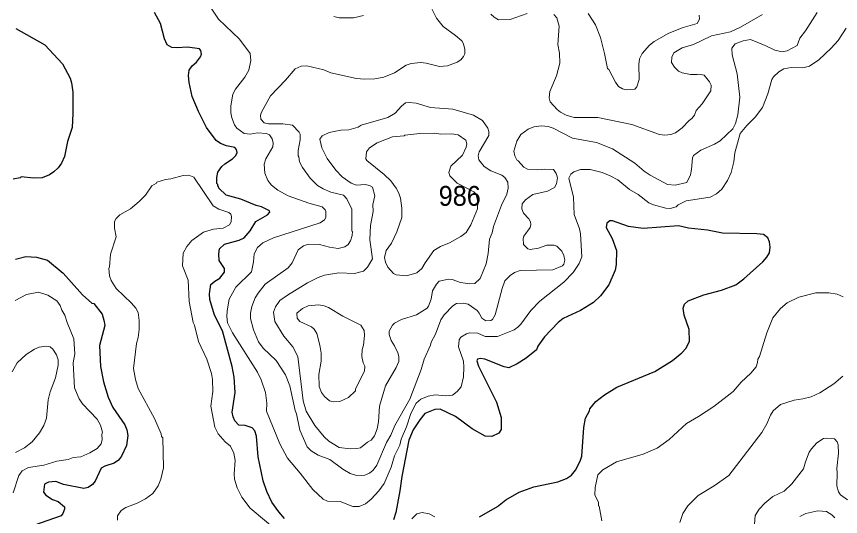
# Model space of a CAD drawing. Extents: x 447.8 to 473.9, y 7733.1 to 7760.8.
# Drawn here: x 456.578 to 459.898, y 7741.122 to 7743.138 of the extents above; entities that cross this region are included whole.
import ezdxf

# ---------------------------------------------------------------- set-up
doc = ezdxf.new("R2010")
doc.units = 0
doc.header["$LTSCALE"] = 0.032
doc.layers.add('1', color=7, linetype='Continuous', lineweight=25)
doc.layers.add('2', color=7, linetype='Continuous', lineweight=13)
doc.layers.add('21', color=7, linetype='Continuous')

msp = doc.modelspace()

# ---------------------------------------------------------------- linework, layer by layer
at = {"layer": '1'}
for points in [[(457.271, 7742.9008), (457.2733, 7742.9223), (457.2854, 7742.9399), (457.3039, 7742.9547), (457.319, 7742.9752), (457.3237, 7742.9862), (457.3213, 7743.0016), (457.3152, 7743.0082), (457.2669, 7743.0153), (457.2261, 7743.0114), (457.2045, 7743.013), (457.1858, 7743.0245), (457.1745, 7743.0482), (457.1587, 7743.1099), (457.1342, 7743.1542)], [(456.5753, 7743.0905), (456.6929, 7743.024), (456.7637, 7742.9477), (456.7947, 7742.8902), (456.8005, 7742.8707), (456.8052, 7742.8333), (456.8051, 7742.7468), (456.802, 7742.6914), (456.7844, 7742.6341), (456.7723, 7742.5744), (456.7597, 7742.5476), (456.7456, 7742.5277), (456.7287, 7742.5117), (456.7113, 7742.5004), (456.6822, 7742.4879), (456.6473, 7742.4871), (456.5969, 7742.4917), (456.5925, 7742.4879), (456.5648, 7742.4822)], [(457.3824, 7742.638), (457.3439, 7742.6914), (457.3114, 7742.7548), (457.2855, 7742.8162), (457.2732, 7742.8725), (457.271, 7742.9008)], [(457.6583, 7741.1137), (457.6354, 7741.1407), (457.6072, 7741.1806), (457.5861, 7741.2226), (457.572, 7741.2661), (457.5514, 7741.3624), (457.545, 7741.4458), (457.5378, 7741.4674), (457.5275, 7741.48), (457.4993, 7741.4891), (457.4736, 7741.491), (457.4582, 7741.5077), (457.4513, 7741.5239), (457.4474, 7741.5429), (457.4592, 7741.623), (457.4545, 7741.6844), (457.4472, 7741.7267), (457.4083, 7741.8714), (457.3761, 7741.9345), (457.3575, 7741.9977), (457.3561, 7742.0208), (457.3615, 7742.0578), (457.3773, 7742.0716), (457.3975, 7742.0831), (457.416, 7742.1075), (457.4158, 7742.1226), (457.395, 7742.1546), (457.3928, 7742.182), (457.3964, 7742.2022), (457.4168, 7742.2204), (457.4759, 7742.2361), (457.4961, 7742.2459), (457.5199, 7742.2738), (457.5419, 7742.3123), (457.59, 7742.3383), (457.5986, 7742.349), (457.5973, 7742.3552), (457.5655, 7742.3707), (457.5439, 7742.3758), (457.4821, 7742.402), (457.4233, 7742.4182), (457.393, 7742.4468), (457.3925, 7742.4525), (457.3888, 7742.4546), (457.3887, 7742.4611), (457.3856, 7742.465), (457.3855, 7742.4887), (457.3892, 7742.5112), (457.4059, 7742.5337), (457.4176, 7742.5447), (457.448, 7742.5649), (457.4615, 7742.5778), (457.4666, 7742.5897), (457.4649, 7742.6015), (457.4573, 7742.6105), (457.4237, 7742.6163), (457.3997, 7742.6259), (457.3824, 7742.638)], [(458.4434, 7741.1209), (458.5159, 7741.1624), (458.5497, 7741.1895), (458.6036, 7741.2204), (458.662, 7741.2415), (458.7586, 7741.2617), (458.7934, 7741.276), (458.8143, 7741.2893), (458.83, 7741.3093), (458.8491, 7741.3461), (458.8556, 7741.3657), (458.8636, 7741.4808), (458.8708, 7741.5192), (458.8867, 7741.549), (458.8873, 7741.5567), (458.9123, 7741.5867), (458.9474, 7741.6134), (458.9964, 7741.6445), (459.1504, 7741.7071), (459.2204, 7741.7516), (459.2582, 7741.782), (459.2743, 7741.7994), (459.2901, 7741.8285), (459.2878, 7741.8767), (459.2686, 7741.9345), (459.2645, 7741.9629), (459.2698, 7741.9786), (459.2841, 7741.9925), (459.3474, 7742.0159), (459.418, 7742.0348), (459.4759, 7742.0571), (459.5079, 7742.0804), (459.5843, 7742.1495), (459.6006, 7742.1686), (459.6117, 7742.1852), (459.6151, 7742.2087), (459.6116, 7742.2296), (459.6045, 7742.2462), (459.5882, 7742.2587), (459.5603, 7742.2624), (459.4223, 7742.265), (459.3622, 7742.277), (459.2861, 7742.2849), (459.2456, 7742.2946), (459.1033, 7742.2835), (459.0432, 7742.2919), (458.9791, 7742.3147), (458.9681, 7742.3146), (458.9567, 7742.3046), (458.9536, 7742.2878), (458.9773, 7742.2429), (458.9951, 7742.1942), (458.9936, 7742.1388), (458.9898, 7742.116), (458.965, 7742.0558), (458.9315, 7742.0122), (458.9024, 7741.9855), (458.8505, 7741.9523), (458.7808, 7741.9201), (458.7601, 7741.9039), (458.7055, 7741.8473)], [(456.574, 7742.1599), (456.616, 7742.1704), (456.6593, 7742.1677), (456.7037, 7742.1558), (456.7665, 7742.1034), (456.8447, 7742.0163), (456.8819, 7741.9831), (456.8901, 7741.9811), (456.9237, 7741.9376), (456.9319, 7741.9088), (456.9335, 7741.8925), (456.9127, 7741.8113), (456.9167, 7741.7276), (456.9286, 7741.6658), (456.9478, 7741.6029), (456.9667, 7741.562), (457.0152, 7741.4923), (457.0231, 7741.4718), (457.0264, 7741.4491), (457.0215, 7741.4086), (457.0018, 7741.366), (456.9889, 7741.3491), (456.9719, 7741.3377), (456.9347, 7741.3254), (456.9194, 7741.3168), (456.8953, 7741.2646), (456.8845, 7741.2518), (456.8672, 7741.2388), (456.8498, 7741.2359), (456.7671, 7741.2517), (456.7362, 7741.263), (456.7067, 7741.2614), (456.6909, 7741.2527), (456.6874, 7741.2207), (456.6969, 7741.2081), (456.7232, 7741.1907), (456.7464, 7741.1824), (456.7711, 7741.1608), (456.7715, 7741.1524), (456.7654, 7741.1346), (456.7579, 7741.1253), (456.6241, 7741.0786)], [(458.7055, 7741.8473), (458.6782, 7741.8088), (458.6725, 7741.7949), (458.6321, 7741.7611), (458.5946, 7741.7377), (458.5614, 7741.7217)], [(458.5614, 7741.7217), (458.5427, 7741.7257), (458.4656, 7741.757), (458.4472, 7741.76), (458.4348, 7741.7573), (458.4326, 7741.7501), (458.4392, 7741.7287), (458.5125, 7741.5837), (458.5302, 7741.5211), (458.5302, 7741.4733), (458.5211, 7741.4585), (458.4925, 7741.4443), (458.4661, 7741.4467), (458.4136, 7741.4765), (458.3471, 7741.5261), (458.2846, 7741.5548), (458.2642, 7741.554), (458.2239, 7741.5377), (458.2026, 7741.5124), (458.1761, 7741.4717), (458.1584, 7741.4302), (458.131, 7741.2839), (458.1231, 7741.2256), (458.1062, 7741.1384), (458.0975, 7741.109)]]:
    msp.add_lwpolyline(points, dxfattribs=at)
at = {"layer": '2'}
for points in [[(457.5203, 7741.9419), (457.5258, 7741.9686), (457.5401, 7742.0034), (457.5518, 7742.0224), (457.5806, 7742.0586), (457.673, 7742.1252), (457.6888, 7742.1454), (457.7131, 7742.1981), (457.7348, 7742.2132), (457.7542, 7742.2201), (457.7988, 7742.2186), (457.8387, 7742.2079), (457.8737, 7742.2026), (457.9011, 7742.2103), (457.914, 7742.2188), (457.9234, 7742.2345), (457.9308, 7742.2555), (457.9314, 7742.2711), (457.9291, 7742.2734), (457.929, 7742.3609), (457.9095, 7742.4032), (457.8955, 7742.4182), (457.8447, 7742.4302), (457.8131, 7742.444), (457.7914, 7742.4575), (457.7611, 7742.486), (457.7301, 7742.5298), (457.7188, 7742.5527), (457.7158, 7742.5724), (457.7127, 7742.5772), (457.7127, 7742.5976), (457.7206, 7742.6414), (457.7206, 7742.6639), (457.7172, 7742.6724), (457.6898, 7742.7002), (457.6507, 7742.7051), (457.5933, 7742.7061), (457.5763, 7742.7102), (457.5623, 7742.7247), (457.5615, 7742.74), (457.5648, 7742.7532), (457.6019, 7742.819), (457.6626, 7742.8819), (457.7003, 7742.9277), (457.7253, 7742.9383), (457.7475, 7742.9392), (457.8159, 7742.9237), (457.8443, 7742.9111), (457.9479, 7742.8879), (457.9808, 7742.8855), (458.0218, 7742.8866), (458.0579, 7742.8942), (458.1015, 7742.9109), (458.148, 7742.942), (458.1676, 7742.9487), (458.2066, 7742.9528), (458.2284, 7742.9501), (458.283, 7742.9368), (458.3151, 7742.9391), (458.3535, 7742.9543), (458.3681, 7742.9639), (458.3793, 7742.9768), (458.3843, 7742.9884), (458.3843, 7743.0057), (458.3795, 7743.0279), (458.3727, 7743.0397), (458.3472, 7743.062), (458.2975, 7743.0981), (458.2699, 7743.132), (458.2362, 7743.1994)], [(457.36, 7743.1761), (457.3917, 7743.1276), (457.4761, 7743.0472), (457.5198, 7742.9888), (457.5217, 7742.9607), (457.5136, 7742.9223), (457.4981, 7742.894), (457.4602, 7742.8458), (457.4497, 7742.8249), (457.4422, 7742.7781), (457.4417, 7742.7493), (457.4453, 7742.7298), (457.4566, 7742.7017), (457.4653, 7742.688), (457.4959, 7742.6664), (457.5196, 7742.6643), (457.5498, 7742.669), (457.5848, 7742.6667), (457.5972, 7742.6606), (457.6088, 7742.645), (457.6122, 7742.6279), (457.6114, 7742.6132), (457.5831, 7742.5645), (457.5763, 7742.5423), (457.5786, 7742.5068), (457.5912, 7742.4772), (457.6053, 7742.4588), (457.631, 7742.4385), (457.6732, 7742.4146), (457.7559, 7742.3861), (457.81, 7742.371), (457.8215, 7742.3591), (457.8246, 7742.3521), (457.8245, 7742.3275), (457.8186, 7742.319), (457.8019, 7742.3058), (457.6133, 7742.2458), (457.5711, 7742.2256), (457.549, 7742.2065)], [(458.4895, 7743.1481), (458.502, 7743.1359), (458.5202, 7743.1251), (458.5664, 7743.1258), (458.6355, 7743.1503)], [(459.8038, 7743.1543), (459.7573, 7743.0804), (459.7334, 7743.0506), (459.7228, 7743.0211), (459.6823, 7742.9998), (459.6633, 7742.9961), (459.6338, 7743.002), (459.5949, 7743.022), (459.5357, 7743.0456), (459.5059, 7743.0407), (459.4741, 7743.0283), (459.4601, 7743.0105), (459.4615, 7742.9843), (459.4815, 7742.907), (459.4922, 7742.8132), (459.4842, 7742.7415), (459.4743, 7742.7072), (459.4639, 7742.6857), (459.413, 7742.6372), (459.3905, 7742.623), (459.3353, 7742.5995), (459.3052, 7742.5774), (459.3014, 7742.568), (459.2981, 7742.5215), (459.2939, 7742.5001)], [(457.9762, 7743.1427), (457.9358, 7743.133), (457.878, 7743.1335), (457.8567, 7743.1389)], [(458.7434, 7743.1458), (458.7544, 7743.1324), (458.7647, 7743.0998), (458.7595, 7743.0254), (458.7658, 7742.99), (458.7666, 7742.9505), (458.7542, 7742.8987), (458.7274, 7742.8354), (458.7243, 7742.8098), (458.7288, 7742.7944), (458.7565, 7742.7628), (458.7696, 7742.7521), (458.7922, 7742.7402), (458.8252, 7742.7316), (458.9204, 7742.7307), (459.0567, 7742.7033), (459.1685, 7742.6627)], [(458.881, 7743.15), (458.9105, 7743.1042), (458.9307, 7743.0534), (458.9477, 7742.9887), (458.9592, 7742.928), (458.9648, 7742.9242), (458.9918, 7742.8729), (459.0036, 7742.8563), (459.0196, 7742.8465), (459.0348, 7742.842), (459.0688, 7742.8447), (459.0777, 7742.8551), (459.0867, 7742.884), (459.085, 7742.9451), (459.0876, 7742.9679), (459.0987, 7742.9898), (459.1282, 7743.0233), (459.1469, 7743.038), (459.2056, 7743.0713), (459.2644, 7743.0938), (459.3202, 7743.1106), (459.3292, 7743.1278), (459.3283, 7743.1436)], [(459.1685, 7742.6627), (459.19, 7742.6595), (459.2142, 7742.6622), (459.2324, 7742.6691), (459.2603, 7742.6898), (459.2875, 7742.7184), (459.2991, 7742.727), (459.3092, 7742.7405), (459.3167, 7742.759), (459.34, 7742.7863), (459.3759, 7742.8381), (459.3766, 7742.8612), (459.3705, 7742.8752), (459.348, 7742.9012), (459.327, 7742.9063), (459.3202, 7742.904), (459.2933, 7742.9047), (459.2603, 7742.9118), (459.2453, 7742.9185), (459.2287, 7742.9339), (459.2164, 7742.9526), (459.2178, 7742.9746), (459.2262, 7742.9914), (459.2602, 7743.012), (459.3052, 7743.0252), (459.3784, 7743.061), (459.4543, 7743.0765), (459.4947, 7743.0951), (459.584, 7743.1464)], [(459.8883, 7743.042), (459.9202, 7743.0908)], [(459.6997, 7742.9326), (459.7457, 7742.9312), (459.7731, 7742.9384), (459.8104, 7742.964), (459.8608, 7743.0113), (459.8883, 7743.042)], [(457.4353, 7741.9985), (457.4264, 7741.9515), (457.4257, 7741.9294), (457.4289, 7741.9027), (457.4486, 7741.8629), (457.5487, 7741.7046), (457.5645, 7741.6735), (457.5819, 7741.6217), (457.5866, 7741.5797), (457.586, 7741.5471), (457.6392, 7741.416), (457.6697, 7741.3571), (457.7217, 7741.2973), (457.7725, 7741.2312), (457.8142, 7741.1916), (457.8318, 7741.1837), (457.8827, 7741.1828), (457.9329, 7741.1628), (457.9581, 7741.1622), (457.9844, 7741.1737), (458.0074, 7741.1916), (458.0384, 7741.2264), (458.0589, 7741.256), (458.0871, 7741.3213), (458.1007, 7741.3675), (458.1219, 7741.4099), (458.1285, 7741.4343), (458.1496, 7741.4841), (458.1664, 7741.5373), (458.189, 7741.58), (458.2074, 7741.5954), (458.2372, 7741.6077), (458.2651, 7741.6124), (458.3083, 7741.6086), (458.3351, 7741.6118), (458.3539, 7741.6263), (458.369, 7741.645), (458.3787, 7741.6849), (458.381, 7741.7241), (458.3786, 7741.7488), (458.3595, 7741.8068), (458.3619, 7741.8342), (458.3678, 7741.8452), (458.3908, 7741.8586), (458.403, 7741.8626), (458.4367, 7741.8609), (458.4662, 7741.8484), (458.5166, 7741.8483), (458.5829, 7741.8751), (458.5983, 7741.8851), (458.6106, 7741.8982), (458.6499, 7741.9526), (458.6859, 7741.9903), (458.7836, 7742.0671), (458.8212, 7742.1062), (458.8445, 7742.1418), (458.8562, 7742.1689), (458.8509, 7742.2626), (458.8466, 7742.2828), (458.8244, 7742.3398), (458.8218, 7742.4095), (458.803, 7742.4865), (458.8117, 7742.5031), (458.8238, 7742.5123), (458.8504, 7742.5214), (458.8895, 7742.5214), (458.9383, 7742.5091), (458.97, 7742.4964), (459.0008, 7742.4793), (459.0471, 7742.4411), (459.0833, 7742.4204), (459.1259, 7742.3873), (459.1443, 7742.3788), (459.1941, 7742.365), (459.2121, 7742.3645), (459.2353, 7742.3711), (459.244, 7742.3789), (459.2766, 7742.3948), (459.3723, 7742.4096), (459.3983, 7742.4238), (459.4196, 7742.4428), (459.4428, 7742.4775), (459.457, 7742.5094), (459.4686, 7742.5528), (459.4716, 7742.589), (459.4941, 7742.6664), (459.5206, 7742.6984), (459.5541, 7742.732), (459.5832, 7742.7713), (459.605, 7742.8265), (459.6212, 7742.8849), (459.6281, 7742.8952), (459.65, 7742.9158), (459.6696, 7742.9271), (459.6997, 7742.9326)], [(458.0736, 7742.7309), (458.1034, 7742.749), (458.1289, 7742.7767), (458.145, 7742.79), (458.1596, 7742.7916), (458.1887, 7742.7892), (458.2457, 7742.771), (458.3357, 7742.7653)], [(458.3357, 7742.7653), (458.4199, 7742.741), (458.4558, 7742.7193), (458.4768, 7742.6884), (458.4805, 7742.6744), (458.4806, 7742.6591), (458.4417, 7742.5924), (458.4381, 7742.5769), (458.441, 7742.5598), (458.462, 7742.5329), (458.4888, 7742.5157), (458.5339, 7742.4986), (458.5458, 7742.4898), (458.5582, 7742.47), (458.559, 7742.446), (458.5542, 7742.4222), (458.5317, 7742.3783), (458.4997, 7742.2912), (458.4951, 7742.2657), (458.4837, 7742.2407), (458.4789, 7742.1832), (458.4697, 7742.1413), (458.4462, 7742.0826), (458.4241, 7742.0612), (458.4039, 7742.0599), (458.3675, 7742.0661), (458.3332, 7742.0783), (458.3183, 7742.079), (458.2804, 7742.0711), (458.2696, 7742.0593), (458.254, 7742.0323), (458.2486, 7741.9982), (458.2385, 7741.9704), (458.233, 7741.9624), (458.1891, 7741.9349), (458.1291, 7741.9162), (458.1017, 7741.9019), (458.0925, 7741.8939), (458.0799, 7741.87), (458.079, 7741.8562), (458.0877, 7741.832), (458.1015, 7741.811), (458.1149, 7741.7828), (458.1182, 7741.768), (458.1182, 7741.7476), (458.1071, 7741.7234), (458.0645, 7741.6491), (458.0406, 7741.5674), (458.0363, 7741.5044), (458.0308, 7741.4762), (458.0204, 7741.4475), (458.0071, 7741.4297), (457.9929, 7741.4223), (457.9636, 7741.3999), (457.9491, 7741.3961), (457.9218, 7741.3953), (457.8781, 7741.4001), (457.836, 7741.4261), (457.8174, 7741.4437), (457.7801, 7741.4888), (457.7456, 7741.5465), (457.7327, 7741.5894), (457.711, 7741.7678), (457.6915, 7741.8068), (457.6546, 7741.8501), (457.6186, 7741.9083), (457.6133, 7741.946), (457.6211, 7741.9681), (457.6394, 7741.993), (457.6696, 7742.0151), (457.7505, 7742.064), (457.793, 7742.0863), (457.8184, 7742.0959), (457.8774, 7742.1047), (457.9394, 7742.1024), (457.9756, 7742.1122), (457.992, 7742.1279), (458.0124, 7742.1612), (458.002, 7742.2382), (458.0045, 7742.296), (458.0148, 7742.3516), (458.0133, 7742.3804), (458.0221, 7742.4156), (458.0121, 7742.4503), (458, 7742.4567), (457.9835, 7742.4606), (457.9475, 7742.4583), (457.9262, 7742.4661), (457.8899, 7742.4922), (457.8647, 7742.5186), (457.8292, 7742.5658), (457.8082, 7742.6094), (457.8, 7742.6439), (457.8092, 7742.6572), (457.8385, 7742.6712)], [(457.8385, 7742.6712), (457.8845, 7742.6795), (457.9165, 7742.6811), (457.9541, 7742.6916), (457.9674, 7742.7005), (458.0736, 7742.7309)], [(459.1073, 7742.5148), (459.0694, 7742.5474), (458.9796, 7742.6051), (458.9149, 7742.6305), (458.8177, 7742.6478), (458.7402, 7742.6875), (458.7205, 7742.6943), (458.6929, 7742.698), (458.6619, 7742.6939), (458.6395, 7742.6844), (458.6099, 7742.6621), (458.5945, 7742.6361), (458.5824, 7742.5957), (458.5855, 7742.5761), (458.5949, 7742.5573), (458.5993, 7742.5558), (458.6226, 7742.5304), (458.6364, 7742.5231), (458.6782, 7742.52), (458.7054, 7742.5232), (458.741, 7742.5213), (458.7517, 7742.5049), (458.7579, 7742.4873), (458.7539, 7742.4641), (458.7451, 7742.4491), (458.7172, 7742.4337), (458.6585, 7742.4205), (458.6287, 7742.3994), (458.6155, 7742.3831), (458.6136, 7742.3634), (458.6203, 7742.3453), (458.6418, 7742.3232), (458.6485, 7742.3106), (458.6503, 7742.2994), (458.648, 7742.2874), (458.622, 7742.2529), (458.6192, 7742.2426), (458.6201, 7742.2196), (458.6378, 7742.201), (458.6481, 7742.1994), (458.6816, 7742.2043), (458.7141, 7742.2169), (458.7443, 7742.2162), (458.7554, 7742.2117), (458.7756, 7742.1926), (458.7833, 7742.1743), (458.7866, 7742.1561), (458.7835, 7742.1404), (458.7775, 7742.1331), (458.7392, 7742.1165), (458.6078, 7742.1136), (458.585, 7742.1064), (458.5671, 7742.0943), (458.5462, 7742.0731), (458.5347, 7742.0417), (458.5063, 7741.9357), (458.496, 7741.9169), (458.4885, 7741.9125), (458.4695, 7741.9114), (458.4531, 7741.9215), (458.4424, 7741.9422), (458.4336, 7741.9529), (458.3981, 7741.9789), (458.3795, 7741.9828), (458.3509, 7741.9812), (458.336, 7741.9713), (458.3015, 7741.9361), (458.2879, 7741.915), (458.2659, 7741.8581), (458.2491, 7741.8248), (458.2464, 7741.813), (458.2206, 7741.7562), (458.2081, 7741.7145), (458.1632, 7741.5952), (458.102, 7741.4888), (458.086, 7741.4504), (458.0692, 7741.4214), (458.0302, 7741.3291), (458.0157, 7741.3089), (458.0007, 7741.2965), (457.981, 7741.2889), (457.9683, 7741.2871), (457.9434, 7741.2892), (457.922, 7741.2954), (457.8932, 7741.3128), (457.8408, 7741.352), (457.7936, 7741.3693), (457.7647, 7741.3877), (457.7489, 7741.4027), (457.7191, 7741.4698), (457.7062, 7741.5365), (457.7004, 7741.5491), (457.679, 7741.6491), (457.6623, 7741.694), (457.6241, 7741.7507)], [(457.285, 7742.235), (457.3317, 7742.2692), (457.3715, 7742.2805), (457.4112, 7742.2854), (457.4368, 7742.2989), (457.4432, 7742.3102), (457.4448, 7742.3323), (457.4416, 7742.3416), (457.4336, 7742.3476), (457.3935, 7742.362), (457.3707, 7742.3753), (457.293, 7742.4901), (457.2729, 7742.4983), (457.2497, 7742.4976), (457.2001, 7742.4844), (457.1791, 7742.4815), (457.1438, 7742.4703), (457.1417, 7742.4663), (457.1239, 7742.4562), (457.0977, 7742.4179), (457.0724, 7742.3919), (457.0375, 7742.3623), (456.9941, 7742.3384), (456.9803, 7742.324), (456.9726, 7742.3114), (456.9736, 7742.2846), (456.9799, 7742.2503), (456.9576, 7742.1803), (456.9527, 7742.1296), (456.9496, 7742.1222), (456.9529, 7742.0929), (456.9598, 7742.0745), (456.9804, 7742.0414), (457.0421, 7741.9823), (457.0584, 7741.9627), (457.0682, 7741.9444), (457.0728, 7741.912), (457.0729, 7741.8767), (457.0682, 7741.8438), (457.0615, 7741.8198), (457.0491, 7741.7193), (457.057, 7741.6747), (457.0684, 7741.6388), (457.1348, 7741.5176), (457.1613, 7741.4557), (457.1629, 7741.4443), (457.1675, 7741.4391), (457.1702, 7741.3191), (457.16, 7741.2732), (457.1492, 7741.2457), (457.1269, 7741.2145), (457.0973, 7741.1935), (457.0643, 7741.1761), (457.0183, 7741.1588), (456.9993, 7741.1468), (456.9849, 7741.1257), (456.9848, 7741.108)], [(459.2939, 7742.5001), (459.2782, 7742.4689), (459.2322, 7742.4586), (459.2003, 7742.4611), (459.1311, 7742.4982), (459.1073, 7742.5148)], [(457.2734, 7741.9887), (457.2702, 7742.0755), (457.2476, 7742.1332), (457.2494, 7742.1835), (457.2649, 7742.2116), (457.285, 7742.235)], [(457.549, 7742.2065), (457.5355, 7742.1812), (457.5329, 7742.1495), (457.5254, 7742.109), (457.4619, 7742.0472), (457.4353, 7741.9985)], [(456.5652, 7741.2181), (456.5881, 7741.2873), (456.6007, 7741.3065), (456.6269, 7741.3206), (456.689, 7741.3299), (456.7401, 7741.3449), (456.7859, 7741.3524), (456.8068, 7741.3599), (456.837, 7741.3629), (456.8737, 7741.3791), (456.903, 7741.397), (456.9187, 7741.4159), (456.9236, 7741.4329), (456.9223, 7741.4527), (456.9244, 7741.4625), (456.9172, 7741.4909), (456.9036, 7741.5154), (456.8438, 7741.5766), (456.8312, 7741.597), (456.812, 7741.6406), (456.8072, 7741.7418), (456.8132, 7741.7784), (456.8099, 7741.8381), (456.7822, 7741.9048), (456.773, 7741.9347), (456.7611, 7741.9539), (456.7538, 7741.9731), (456.7401, 7741.9924), (456.7048, 7742.0146), (456.6673, 7742.0264), (456.6192, 7742.0171), (456.5725, 7741.9928)], [(459.9088, 7742.0084), (459.8842, 7742.0182), (459.8511, 7742.0244), (459.7987, 7742.0244), (459.7293, 7742.0062), (459.683, 7741.9835), (459.6557, 7741.9604), (459.6251, 7741.9233), (459.6016, 7741.8624), (459.5711, 7741.7679), (459.5647, 7741.7561), (459.564, 7741.7436), (459.5575, 7741.7254), (459.5371, 7741.7009), (459.4971, 7741.664), (459.4655, 7741.6262), (459.3876, 7741.5664)], [(457.7086, 7740.9972), (457.5197, 7741.1562), (457.4867, 7741.2004), (457.4675, 7741.2383), (457.4565, 7741.2726), (457.4546, 7741.2946), (457.4594, 7741.3479), (457.4543, 7741.3778), (457.4399, 7741.4057), (457.4193, 7741.424), (457.3912, 7741.4554), (457.3775, 7741.483), (457.3608, 7741.5672), (457.3687, 7741.6263), (457.3679, 7741.6753), (457.3639, 7741.6991), (457.3457, 7741.757), (457.3116, 7741.8282), (457.2958, 7741.8936), (457.2903, 7741.905), (457.2734, 7741.9887)], [(457.6241, 7741.7507), (457.5726, 7741.8007), (457.5537, 7741.826), (457.5336, 7741.8755), (457.5206, 7741.9203), (457.5203, 7741.9419)], [(456.5611, 7741.705), (456.5806, 7741.7414), (456.6174, 7741.775), (456.6503, 7741.7964), (456.6692, 7741.805), (456.6972, 7741.8097), (456.7138, 7741.8064), (456.7252, 7741.7967), (456.7398, 7741.7738), (456.746, 7741.754), (456.7459, 7741.7328), (456.7355, 7741.6818), (456.7145, 7741.625), (456.7056, 7741.5923), (456.6995, 7741.5186), (456.6884, 7741.489), (456.6705, 7741.4602), (456.6414, 7741.4239), (456.611, 7741.3992), (456.574, 7741.3809)], [(459.2501, 7741.0983), (459.262, 7741.1345), (459.2827, 7741.1659), (459.3242, 7741.2068), (459.3882, 7741.2464), (459.4477, 7741.2877), (459.5815, 7741.4609), (459.6013, 7741.4958), (459.6157, 7741.5311), (459.627, 7741.5487), (459.6566, 7741.5744), (459.7105, 7741.5918), (459.7458, 7741.5966), (459.7792, 7741.6049), (459.8143, 7741.6213), (459.8714, 7741.657), (459.9067, 7741.6882)], [(459.3876, 7741.5664), (459.326, 7741.5252), (459.2773, 7741.497), (459.2077, 7741.433), (459.1589, 7741.398), (459.1033, 7741.3733)], [(459.5515, 7741.0911), (459.5546, 7741.1265), (459.5696, 7741.1521), (459.5933, 7741.1767), (459.6254, 7741.2031), (459.671, 7741.225), (459.7016, 7741.2537), (459.7488, 7741.3147), (459.7564, 7741.3425), (459.7715, 7741.3811), (459.7803, 7741.3951), (459.8029, 7741.4199), (459.8293, 7741.4362), (459.8429, 7741.4386), (459.8741, 7741.4354), (459.8845, 7741.4237), (459.8881, 7741.4117), (459.8898, 7741.3781), (459.8826, 7741.3153), (459.8848, 7741.2987), (459.8833, 7741.2467), (459.8898, 7741.2214), (459.8973, 7741.2092), (459.9256, 7741.189)], [(459.1033, 7741.3733), (458.9949, 7741.3423), (458.94, 7741.3102), (458.9198, 7741.291), (458.909, 7741.2395), (458.9086, 7741.2096), (458.9229, 7741.1794), (458.923, 7741.1656), (458.9256, 7741.1637), (458.9366, 7741.1047)], [(458.263, 7741.1212), (458.2406, 7741.1334), (458.2124, 7741.1386), (458.1912, 7741.1329), (458.1706, 7741.1126)], [(459.8749, 7741.1174), (459.8624, 7741.1292), (459.8416, 7741.142), (459.8065, 7741.1446), (459.7579, 7741.1339), (459.7333, 7741.1222)]]:
    msp.add_lwpolyline(points, dxfattribs=at)
for points in [[(458.3579, 7742.6614), (458.3881, 7742.6403), (458.3923, 7742.6247), (458.3901, 7742.6119), (458.3745, 7742.5798), (458.3281, 7742.5349), (458.3195, 7742.5098), (458.3234, 7742.4953), (458.3536, 7742.467), (458.4207, 7742.4319), (458.4294, 7742.4223), (458.4364, 7742.3903), (458.4356, 7742.3631), (458.4091, 7742.2987), (458.3896, 7742.2679), (458.368, 7742.251), (458.3232, 7742.2264), (458.286, 7742.2111), (458.2599, 7742.1943), (458.2242, 7742.1451), (458.2112, 7742.1218), (458.1911, 7742.1053), (458.15, 7742.0928), (458.1072, 7742.0967), (458.0966, 7742.1022), (458.0737, 7742.1278), (458.0643, 7742.1473), (458.0614, 7742.1665), (458.0674, 7742.1946), (458.0885, 7742.225), (458.1107, 7742.2707), (458.1302, 7742.3275), (458.1302, 7742.366), (458.1255, 7742.4059), (458.1189, 7742.4256), (458.1077, 7742.4461), (458.0857, 7742.4755), (458.0592, 7742.5019), (457.9893, 7742.5582), (457.9851, 7742.5647), (457.9886, 7742.5926), (458.0003, 7742.6089), (458.0307, 7742.6285), (458.0925, 7742.653), (458.1404, 7742.6571), (458.1426, 7742.6602), (458.2033, 7742.6667), (458.2631, 7742.6681), (458.2872, 7742.6643), (458.3312, 7742.6659)], [(457.8924, 7741.9298), (457.8347, 7741.9651), (457.8181, 7741.9717), (457.7946, 7741.9756), (457.7536, 7741.9722), (457.7302, 7741.9612), (457.7071, 7741.9417), (457.7095, 7741.9222), (457.7195, 7741.9082), (457.7661, 7741.8871), (457.7772, 7741.8782), (457.7882, 7741.8604), (457.8008, 7741.8126), (457.8055, 7741.7814), (457.8055, 7741.7485), (457.7968, 7741.6953), (457.7976, 7741.6459), (457.8069, 7741.6227), (457.8185, 7741.6068), (457.8397, 7741.5889), (457.8546, 7741.5847), (457.8806, 7741.5861), (457.9159, 7741.6025), (457.9434, 7741.6284), (457.9446, 7741.6376), (457.9803, 7741.7088), (457.9811, 7741.7284), (457.9754, 7741.7414), (457.9699, 7741.7669), (457.9714, 7741.7959), (457.9762, 7741.8126), (457.9803, 7741.8524), (457.9789, 7741.8723), (457.9659, 7741.8939)]]:
    msp.add_lwpolyline(points, close=True, dxfattribs=at)

# ---------------------------------------------------------------- texts
at = {"layer": '21', "width": 0.95}
msp.add_text('986', height=0.08, dxfattribs=at).set_placement((458.2791, 7742.3751))

doc.saveas('drawing.dxf')
